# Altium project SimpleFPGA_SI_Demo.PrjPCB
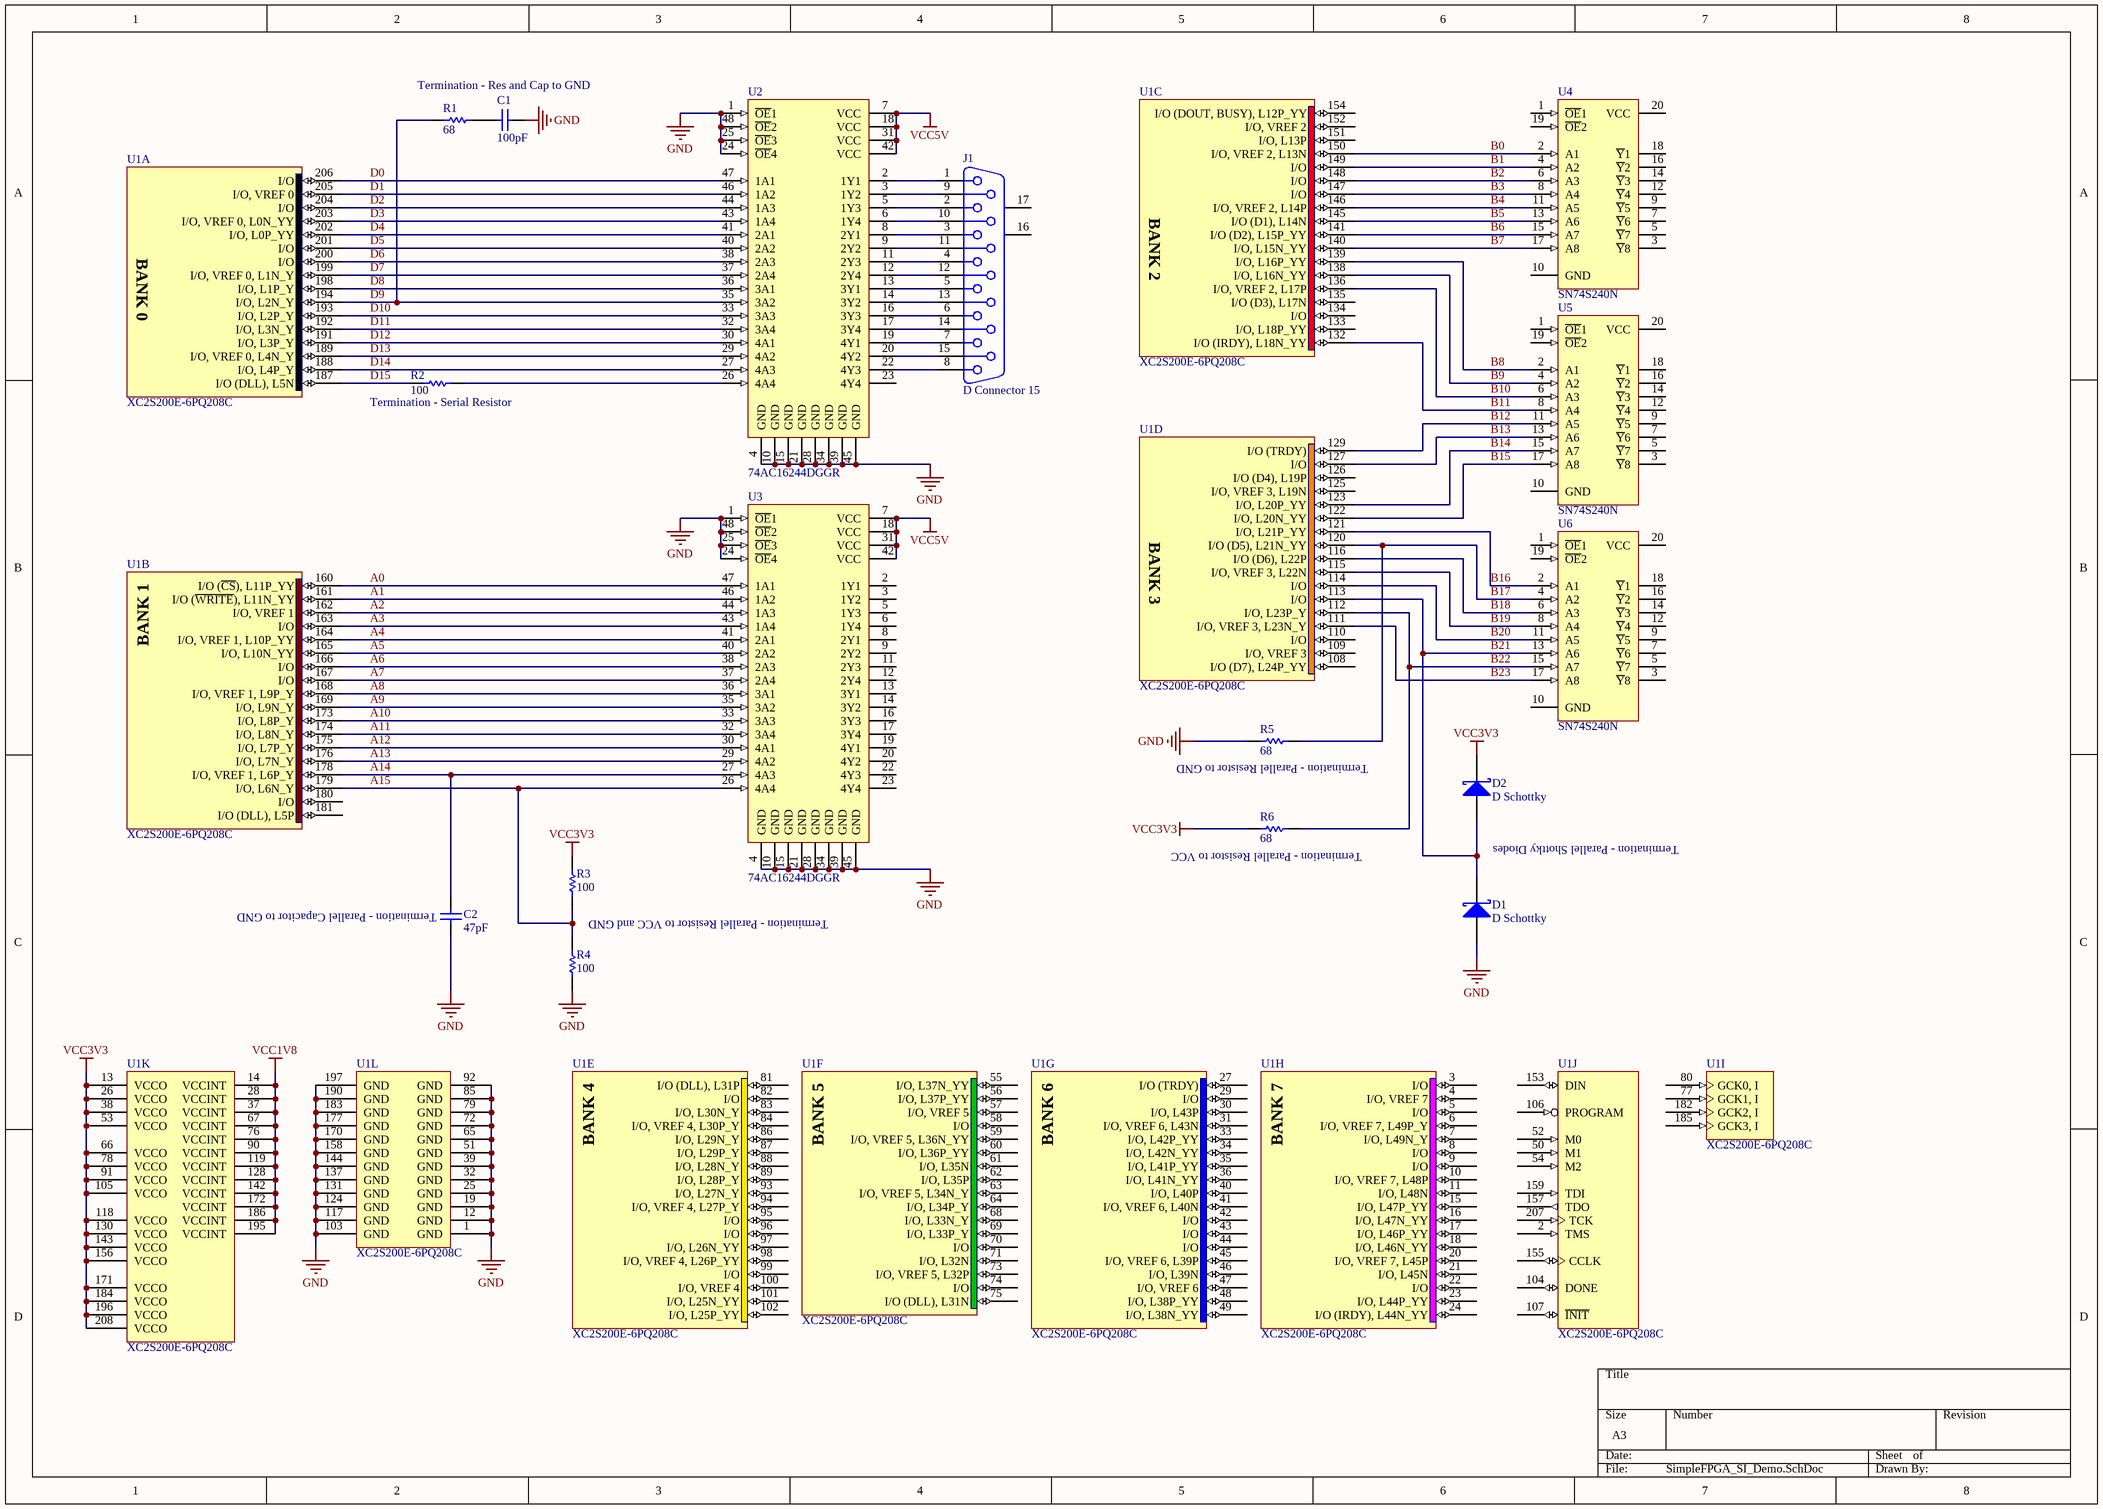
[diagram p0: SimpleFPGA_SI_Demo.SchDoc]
1 sheet, 17 parts. Net scope: global (net labels, ports and power ports of the same name join across sheets).
Board file: SI_Demo.PcbDoc

## Sheet SimpleFPGA_SI_Demo.SchDoc
size A3

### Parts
C1  value 100pF  [RAD-0.3]  (hidden comment: Cap)
C2  value 47pF  [RAD-0.3]  (hidden comment: Cap)
D1  D Schottky  [SMB]
D2  D Schottky  [SMB]
J1  D Connector 15  [DSUB1.385-2H15]
R1  value 68  [AXIAL-0.3]  (hidden comment: Res1)
R2  value 100  [AXIAL-0.3]  (hidden comment: Res1)
R3  value 100  [AXIAL-0.3]  (hidden comment: Res1)
R4  value 100  [AXIAL-0.3]  (hidden comment: Res1)
R5  value 68  [AXIAL-0.3]  (hidden comment: Res1)
R6  value 68  [AXIAL-0.3]  (hidden comment: Res1)
U1  XC2S200E-6PQ208C  [PQ208_N]  (parts A,B,C,D,E,F,G,H,I,J,K,L of 12)
U2  74AC16244DGGR  [DGG048]
U3  74AC16244DGGR  [DGG048]
U4  SN74S240N  [N020]
U5  SN74S240N  [N020]
U6  SN74S240N  [N020]

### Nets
GND: C1.2 C2.1 D1.1(A) R4.1 R5.1 U1.1(GND) U1.12(GND) U1.19(GND) U1.25(GND) U1.32(GND) U1.39(GND) U1.51(GND) U1.65(GND) U1.72(GND) U1.79(GND) U1.85(GND) U1.92(GND) U1.103(GND) U1.117(GND) U1.124(GND) U1.131(GND) U1.137(GND) U1.144(GND) U1.158(GND) U1.170(GND) U1.177(GND) U1.183(GND) U1.190(GND) U1.197(GND) U2.1(~{OE}1) U2.4(GND) U2.10(GND) U2.15(GND) U2.21(GND) U2.24(~{OE}4) U2.25(~{OE}3) U2.28(GND) U2.34(GND) U2.39(GND) U2.45(GND) U2.48(~{OE}2) U3.1(~{OE}1) U3.4(GND) U3.10(GND) U3.15(GND) U3.21(GND) U3.24(~{OE}4) U3.25(~{OE}3) U3.28(GND) U3.34(GND) U3.39(GND) U3.45(GND) U3.48(~{OE}2)
VCC1V8: U1.14(VCCINT) U1.28(VCCINT) U1.37(VCCINT) U1.67(VCCINT) U1.76(VCCINT) U1.90(VCCINT) U1.119(VCCINT) U1.128(VCCINT) U1.142(VCCINT) U1.172(VCCINT) U1.186(VCCINT) U1.195(VCCINT)
VCC3V3: D2.2(K) R3.2 R6.1 U1.13(VCCO) U1.26(VCCO) U1.38(VCCO) U1.53(VCCO) U1.66(VCCO) U1.78(VCCO) U1.91(VCCO) U1.105(VCCO) U1.118(VCCO) U1.130(VCCO) U1.143(VCCO) U1.156(VCCO) U1.171(VCCO) U1.184(VCCO) U1.196(VCCO) U1.208(VCCO)
VCC5V: U2.7(VCC) U2.18(VCC) U2.31(VCC) U2.42(VCC) U3.7(VCC) U3.18(VCC) U3.31(VCC) U3.42(VCC)
A0: U1.160(I/O_(~{CS}),_L11P_YY) U3.47(1A1)
A1: U1.161(I/O_(~{WRITE}),_L11N_YY) U3.46(1A2)
A2: U1.162(I/O,_VREF_1) U3.44(1A3)
A3: U1.163(I/O) U3.43(1A4)
A4: U1.164(I/O,_VREF_1,_L10P_YY) U3.41(2A1)
A5: U1.165(I/O,_L10N_YY) U3.40(2A2)
A6: U1.166(I/O) U3.38(2A3)
A7: U1.167(I/O) U3.37(2A4)
A8: U1.168(I/O,_VREF_1,_L9P_Y) U3.36(3A1)
A9: U1.169(I/O,_L9N_Y) U3.35(3A2)
A10: U1.173(I/O,_L8P_Y) U3.33(3A3)
A11: U1.174(I/O,_L8N_Y) U3.32(3A4)
A12: U1.175(I/O,_L7P_Y) U3.30(4A1)
A13: U1.176(I/O,_L7N_Y) U3.29(4A2)
A14: C2.2 U1.178(I/O,_VREF_1,_L6P_Y) U3.27(4A3)
A15: R3.1 R4.2 U1.179(I/O,_L6N_Y) U3.26(4A4)
B0: U1.150(I/O,_VREF_2,_L13N) U4.2(A1)
B1: U1.149(I/O) U4.4(A2)
B2: U1.148(I/O) U4.6(A3)
B3: U1.147(I/O) U4.8(A4)
B4: U1.146(I/O,_VREF_2,_L14P) U4.11(A5)
B5: U1.145(I/O_(D1),_L14N) U4.13(A6)
B6: U1.141(I/O_(D2),_L15P_YY) U4.15(A7)
B7: U1.140(I/O,_L15N_YY) U4.17(A8)
B8: U1.139(I/O,_L16P_YY) U5.2(A1)
B9: U1.138(I/O,_L16N_YY) U5.4(A2)
B10: U1.136(I/O,_VREF_2,_L17P) U5.6(A3)
B11: U1.132(I/O_(IRDY),_L18N_YY) U5.8(A4)
B12: U1.129(I/O_(TRDY)) U5.11(A5)
B13: U1.127(I/O) U5.13(A6)
B14: U1.123(I/O,_L20P_YY) U5.15(A7)
B15: U1.122(I/O,_L20N_YY) U5.17(A8)
B16: U1.121(I/O,_L21P_YY) U6.2(A1)
B17: R5.2 U1.120(I/O_(D5),_L21N_YY) U6.4(A2)
B18: U1.116(I/O_(D6),_L22P) U6.6(A3)
B19: U1.115(I/O,_VREF_3,_L22N) U6.8(A4)
B20: U1.114(I/O) U6.11(A5)
B21: D1.2(K) D2.1(A) U1.113(I/O) U6.13(A6)
B22: R6.2 U1.112(I/O,_L23P_Y) U6.15(A7)
B23: U1.111(I/O,_VREF_3,_L23N_Y) U6.17(A8)
D0: U1.206(I/O) U2.47(1A1)
D1: U1.205(I/O,_VREF_0) U2.46(1A2)
D2: U1.204(I/O) U2.44(1A3)
D3: U1.203(I/O,_VREF_0,_L0N_YY) U2.43(1A4)
D4: U1.202(I/O,_L0P_YY) U2.41(2A1)
D5: U1.201(I/O) U2.40(2A2)
D6: U1.200(I/O) U2.38(2A3)
D7: U1.199(I/O,_VREF_0,_L1N_Y) U2.37(2A4)
D8: U1.198(I/O,_L1P_Y) U2.36(3A1)
D9: R1.1 U1.194(I/O,_L2N_Y) U2.35(3A2)
D10: U1.193(I/O,_L2P_Y) U2.33(3A3)
D11: U1.192(I/O,_L3N_Y) U2.32(3A4)
D12: U1.191(I/O,_L3P_Y) U2.30(4A1)
D13: U1.189(I/O,_VREF_0,_L4N_Y) U2.29(4A2)
D14: U1.188(I/O,_L4P_Y) U2.27(4A3)
D15: R2.1 U1.187(I/O_(DLL),_L5N)
NetC1_1: C1.1 R1.2
NetJ1_1: J1.1 U2.2(1Y1)
NetJ1_2: J1.2 U2.5(1Y3)
NetJ1_3: J1.3 U2.8(2Y1)
NetJ1_4: J1.4 U2.11(2Y3)
NetJ1_5: J1.5 U2.13(3Y1)
NetJ1_6: J1.6 U2.16(3Y3)
NetJ1_7: J1.7 U2.19(4Y1)
NetJ1_8: J1.8 U2.22(4Y3)
NetJ1_9: J1.9 U2.3(1Y2)
NetJ1_10: J1.10 U2.6(1Y4)
NetJ1_11: J1.11 U2.9(2Y2)
NetJ1_12: J1.12 U2.12(2Y4)
NetJ1_13: J1.13 U2.14(3Y2)
NetJ1_14: J1.14 U2.17(3Y4)
NetJ1_15: J1.15 U2.20(4Y2)
NetR2_2: R2.2 U2.26(4A4)

Not connected (* = marked no-connect by the designer): J1 16(MH1) 17(MH2); U1 2(TMS) 3(I/O) 4(I/O,_VREF_7) 5(I/O) 6(I/O,_VREF_7,_L49P_Y) 7(I/O,_L49N_Y) 8(I/O) 9(I/O) 10(I/O,_VREF_7,_L48P) 11(I/O,_L48N) 15(I/O,_L47P_YY) 16(I/O,_L47N_YY) 17(I/O,_L46P_YY) 18(I/O,_L46N_YY) 20(I/O,_VREF_7,_L45P) 21(I/O,_L45N) 22(I/O) 23(I/O,_L44P_YY) 24(I/O_(IRDY),_L44N_YY) 27(I/O_(TRDY)) 29(I/O) 30(I/O,_L43P) 31(I/O,_VREF_6,_L43N) 33(I/O,_L42P_YY) 34(I/O,_L42N_YY) 35(I/O,_L41P_YY) 36(I/O,_L41N_YY) 40(I/O,_L40P) 41(I/O,_VREF_6,_L40N) 42(I/O) 43(I/O) 44(I/O) 45(I/O,_VREF_6,_L39P) 46(I/O,_L39N) 47(I/O,_VREF_6) 48(I/O,_L38P_YY) 49(I/O,_L38N_YY) 50(M1) 52(M0) 54(M2) 55(I/O,_L37N_YY) 56(I/O,_L37P_YY) 57(I/O,_VREF_5) 58(I/O) 59(I/O,_VREF_5,_L36N_YY) 60(I/O,_L36P_YY) 61(I/O,_L35N) 62(I/O,_L35P) 63(I/O,_VREF_5,_L34N_Y) 64(I/O,_L34P_Y) 68(I/O,_L33N_Y) 69(I/O,_L33P_Y) 70(I/O) 71(I/O,_L32N) 73(I/O,_VREF_5,_L32P) 74(I/O) 75(I/O_(DLL),_L31N) 77(GCK1,_I) 80(GCK0,_I) 81(I/O_(DLL),_L31P) 82(I/O) 83(I/O,_L30N_Y) 84(I/O,_VREF_4,_L30P_Y) 86(I/O,_L29N_Y) 87(I/O,_L29P_Y) 88(I/O,_L28N_Y) 89(I/O,_L28P_Y) 93(I/O,_L27N_Y) 94(I/O,_VREF_4,_L27P_Y) 95(I/O) 96(I/O) 97(I/O,_L26N_YY) 98(I/O,_VREF_4,_L26P_YY) 99(I/O) 100(I/O,_VREF_4) 101(I/O,_L25N_YY) 102(I/O,_L25P_YY) 104(DONE) 106(PROGRAM) 107(~{INIT}) 108(I/O_(D7),_L24P_YY) 109(I/O,_VREF_3) 110(I/O) 125(I/O,_VREF_3,_L19N) 126(I/O_(D4),_L19P) 133(I/O,_L18P_YY) 134(I/O) 135(I/O_(D3),_L17N) 151(I/O,_L13P) 152(I/O,_VREF_2) 153(DIN) 154(I/O_(DOUT,_BUSY),_L12P_YY) 155(CCLK) 157(TDO) 159(TDI) 180(I/O) 181(I/O_(DLL),_L5P) 182(GCK2,_I) 185(GCK3,_I) 207(TCK); U2 23(4Y4); U3 2(1Y1) 3(1Y2) 5(1Y3) 6(1Y4) 8(2Y1) 9(2Y2) 11(2Y3) 12(2Y4) 13(3Y1) 14(3Y2) 16(3Y3) 17(3Y4) 19(4Y1) 20(4Y2) 22(4Y3) 23(4Y4); U4 1(~{OE}1) 3(~{Y}8) 5(~{Y}7) 7(~{Y}6) 9(~{Y}5) 10(GND) 12(~{Y}4) 14(~{Y}3) 16(~{Y}2) 18(~{Y}1) 19(~{OE}2) 20(VCC); U5 1(~{OE}1) 3(~{Y}8) 5(~{Y}7) 7(~{Y}6) 9(~{Y}5) 10(GND) 12(~{Y}4) 14(~{Y}3) 16(~{Y}2) 18(~{Y}1) 19(~{OE}2) 20(VCC); U6 1(~{OE}1) 3(~{Y}8) 5(~{Y}7) 7(~{Y}6) 9(~{Y}5) 10(GND) 12(~{Y}4) 14(~{Y}3) 16(~{Y}2) 18(~{Y}1) 19(~{OE}2) 20(VCC)

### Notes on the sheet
- Termination - Res and Cap to GND
- (near R2) Termination - Serial Resistor
- (near R5) Termination - Parallel Resistor to GND
- (near R6) Termination - Parallel Resistor to VCC
- Termination - Parallel Shottky Diodes
- (near C2) Termination - Parallel Capacitor to GND
- Termination - Parallel Resistor to VCC and GND

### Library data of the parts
C1 C2 = Cap: Capacitor
D1 D2 = D Schottky: Schottky Diode
J1 = D Connector 15: Receptacle Assembly, 15 Position, Right Angle; PackageDocument: O; Positions: 15
R1-R6 = Res1: Resistor
U1 = XC2S200E-6PQ208C: Spartan-IIE 1.8V FPGA, 208-Pin PQFP, Standard Performance, Commercial Grade
U2 U3 = 74AC16244DGGR: 16-Bit Buffer/Line Driver with 3-State Outputs
U4-U6 = SN74S240N: Octal Buffer and Line Driver with 3-State Outputs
